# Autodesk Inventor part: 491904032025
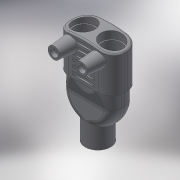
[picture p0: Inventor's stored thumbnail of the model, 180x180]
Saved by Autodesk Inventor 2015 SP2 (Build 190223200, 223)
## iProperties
Created: 2017-07
Part Number: 491904032025
Material: Generic
Description: PLASSON REDUCING Y 32X25X25
Document SubType Name: Modeling
Designer: KIM
Density: 1 g/cm^3
Appearance: Default
Author: KIM
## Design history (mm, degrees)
derived "491904.ipt"
feature "Solid1::491904.ipt"
tag "TaggingFeature1"
body "Solid1"
other parameters: "d1" = 99, "d2" = 19.8, "d3" = 7, "d4" = 79.2, "d5" = 42, "d6" = 36, "d7" = 0, "d8" = 29.7, "d9" = 29.7, "d10" = 16.2, "d11" = 1.8, "d12" = -19.8, "d13" = 16.2, "d14" = 28, "d15" = 49.5, "d16" = 0, "d17" = -3.96, "d18" = 3.96, "d19" = 0, "d22" = 7.425, "d32" = 25, "d33" = 25, "d34" = 35, "d35" = 17.5, "d37" = 0, "d38" = 27.5, "d39" = 27.5, "d41" = 0, "d42" = 22.5, "d43" = 180 deg, "d52" = 99, "d53" = 94.05, "d54" = 49.5, "d55" = 63, "d56" = 31.5, "d57" = 21, "d58" = 119, "d59" = 32, "d60" = 25.6, "d62" = 14.4, "d64" = 0, "d66" = 0.32, "d71" = 11.88, "d72" = 1.19, "d73" = 7.04, "d74" = 16, "d75" = 59.4, "d76" = 0, "d77" = 6.4, "d78" = 38, "d79" = 15, "d80" = 15, "d81" = 22.95, "d82" = 5 deg, "d83" = 4, "d84" = 4, "d87" = 14, "d88" = 0, "d89" = 3.57, "d90" = 3, "d91" = 0, "d_1" = 25, "L_" = 36, "H_1" = 99, "d_2" = 12, "d_" = 32, "H_" = 119, "A_" = 38
